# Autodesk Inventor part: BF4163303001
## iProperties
Shininess: 64.0
Angle Display Precision: 2
Document Length Units: 11272
Document Angle Units: 11279
Document Time Units: 11290
Document Mass Units: 11286
Document Length Units Precision: 3
Document Angle Units Precision: 2
Created: 2003-05
Part Number: BF4163303001
Material: Bronze, Soft Tin
Description: 1/8 COUPLING, FULL, 125 LB RED BRASS, NPT
Vendor: BF4163303001
Document SubType Name: Modeling
Designer: RCOPE
Density: 8.874
Volumn: 3.117073479443971
Area: 22.46133558620172
PropertySet Name: Model Information
Control State: 0
Master: False
Checked Out: False
Title: COUPLING, FULL, 125 LB RED BRASS, NPT
Author: RCOPE
Revision Number: 0
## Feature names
1. Revolution1
2. Extrusion1
3. Extrusion2
4. Extrusion3
5. Extrusion4
6. Fillet1
